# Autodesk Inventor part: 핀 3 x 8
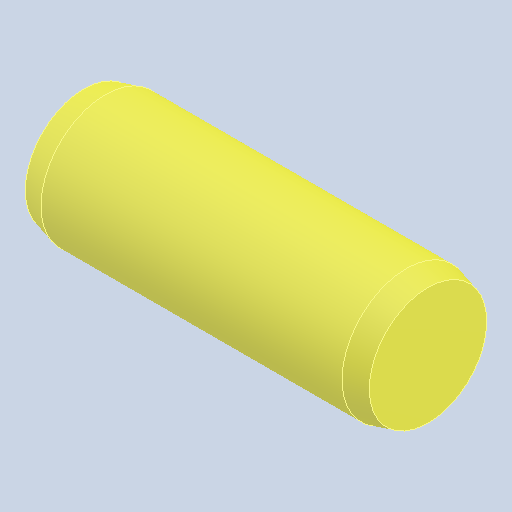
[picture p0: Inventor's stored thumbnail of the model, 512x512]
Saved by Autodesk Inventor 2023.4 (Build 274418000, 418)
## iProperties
Created: 2024-04
Part Number: 핀 3 x 8
Material: 강철, 연강
Description: 평행 핀
Document SubType Name: Modeling
Designer: EDU
Density: 7.85 g/cm^3
Appearance: 기본값
Author: jhkim
Sending System: Autodesk Inventor 2025
Preprocessor: ST-DEVELOPER v20
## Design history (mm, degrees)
node "핀 3 x 81"
node "솔리드1"
body "Solid1"
